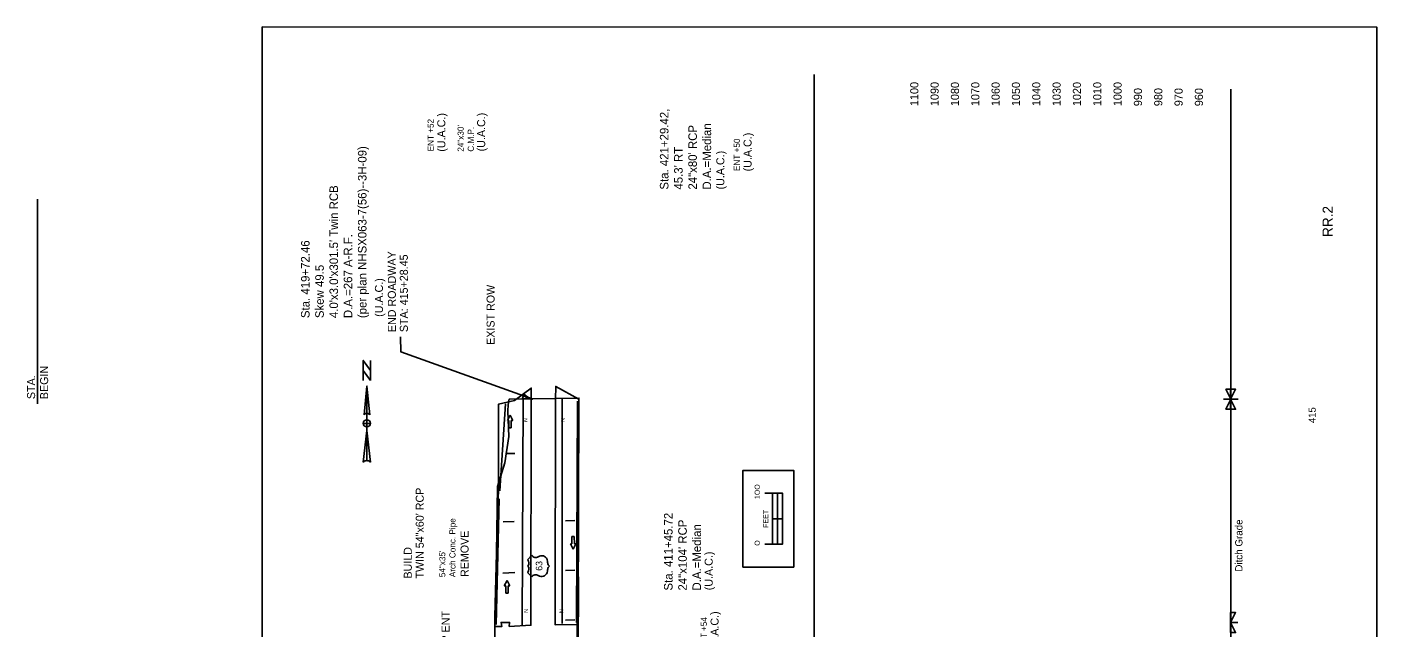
# Model space of a CAD drawing. Extents: x 15474972 to 15478172, y 8962633 to 8965955.
# Drawn here: x 15475516 to 15478172, y 8964774 to 8965955 of the extents above; entities that cross this region are included whole.
import ezdxf

# ---------------------------------------------------------------- set-up
doc = ezdxf.new("R2010")
doc.units = 0
for name, color, linetype in [('brgDimensionLines', 7, 'Continuous'), ('brgTextNormal', 7, 'Continuous'), ('Default', 7, 'Continuous'), ('dsnTextCpn', 7, 'Continuous'), ('dsnTextFinalPlan', 7, 'Continuous'), ('Existing_Right_of_Way', 7, 'Continuous'), ('Level 50', 7, 'Continuous'), ('rowdsnLineProposed', 7, 'Continuous'), ('rowdsnOverlap10', 7, 'Continuous'), ('rowdsnOverlap9', 7, 'Continuous'), ('rowdsnParcelML', 7, 'Continuous'), ('rowdsnParcelSR', 7, 'Continuous'), ('rowdsnPSConstructPlot', 7, 'Continuous'), ('rowdsnSecLines', 7, 'Continuous'), ('rowdsnShapeFeeTitle', 7, 'Continuous'), ('rowdsnStationML', 7, 'Continuous'), ('rowdsnSymbolsExisting', 7, 'Continuous'), ('rowdsnSymbolsOther', 7, 'Continuous'), ('rowdsnSymbolsProposed', 7, 'Continuous'), ('SurTxtDrainage', 7, 'Continuous')]:
    doc.layers.add(name, color=color, linetype=linetype)

msp = doc.modelspace()

# ---------------------------------------------------------------- linework, layer by layer
at = {"layer": 'brgDimensionLines'}
for p, q in [((15476500.8, 8964906.3), (15476508.8, 8964915.1)), ((15476500.8, 8964906.3), (15476508.8, 8964915.1)), ((15476538.9, 8964906.9), (15476539.2, 8964906.1)), ((15476538.9, 8964906.9), (15476539.2, 8964906.1)), ((15476540.1, 8964900.9), (15476540.2, 8964899.8)), ((15476540.1, 8964900.9), (15476540.2, 8964899.8)), ((15476508.8, 8964872.4), (15476500.8, 8964881.2)), ((15476508.8, 8964872.4), (15476500.8, 8964881.2)), ((15476539.1, 8964881.4), (15476538.9, 8964880.6)), ((15476539.1, 8964881.4), (15476538.9, 8964880.6)), ((15476540.2, 8964887.7), (15476540.1, 8964886.6)), ((15476540.2, 8964887.7), (15476540.1, 8964886.6))]:
    msp.add_line(p, q, dxfattribs=at)
for centre, radius, start, end in [((15476494.1, 8964899.9), 9.26, 318.2023, 43.3357), ((15476494.1, 8964899.9), 9.26, 318.2023, 43.3357), ((15476494.1, 8964887.6), 9.26, 316.6383, 41.7717), ((15476494.1, 8964887.6), 9.26, 316.6383, 41.7717), ((15476516.7, 8964920), 9.28, 211.4945, 303.0945), ((15476516.7, 8964920), 9.28, 211.4945, 303.0945), ((15476528.3, 8964903), 11.3, 19.6285, 125.345), ((15476528.3, 8964903), 11.3, 19.6285, 125.345), ((15476513.8, 8964898.7), 26.4, 4.9374, 16.5073), ((15476513.8, 8964898.7), 26.4, 4.9374, 16.5073), ((15476548, 8964900.2), 7.75, 182.5463, 236.993), ((15476548, 8964900.2), 7.75, 182.5463, 236.993), ((15476548, 8964887.3), 7.75, 122.981, 177.4277), ((15476548, 8964887.3), 7.75, 122.981, 177.4277), ((15476516.7, 8964867.6), 9.28, 56.8795, 148.4795), ((15476516.7, 8964867.6), 9.28, 56.8795, 148.4795), ((15476528.3, 8964884.5), 11.3, 234.629, 340.3455), ((15476528.3, 8964884.5), 11.3, 234.629, 340.3455), ((15476513.8, 8964888.8), 26.4, 343.4667, 355.0366), ((15476513.8, 8964888.8), 26.4, 343.4667, 355.0366)]:
    msp.add_arc(centre, radius, start, end, dxfattribs=at)
at = {"layer": 'brgTextNormal'}
for p, q in [((15475536.6, 8965213.4), (15475536.7, 8965616.1)), ((15476184.4, 8965247.9), (15476190.1, 8965191.6)), ((15476184.4, 8965247.9), (15476184.4, 8965101.4)), ((15476178.8, 8965191.6), (15476178.8, 8965191.6)), ((15476179, 8965192.1), (15476180.1, 8965193.3)), ((15476177.4, 8965098.6), (15476184.4, 8965160.6)), ((15476184.4, 8965167.6), (15476184.4, 8965167.6))]:
    msp.add_line(p, q, dxfattribs=at)
msp.add_lwpolyline([(15476191.5, 8965259.2), (15476177.4, 8965278.9), (15476177.4, 8965298.6), (15476191.5, 8965278.9)], close=True, dxfattribs=at)
for points in [[(15476177.4, 8965259.2), (15476177.4, 8965298.6), (15476191.5, 8965278.9), (15476191.5, 8965298.6)], [(15476178.8, 8965191.6), (15476184.4, 8965247.9), (15476184.4, 8965194.4)], [(15476184.4, 8965167.6), (15476184.4, 8965174.7), (15476177.4, 8965174.7)], [(15476191.5, 8965174.7), (15476184.4, 8965174.7), (15476184.4, 8965181.7)], [(15476184.4, 8965101.4), (15476184.4, 8965160.6), (15476191.4, 8965098.6)]]:
    msp.add_lwpolyline(points, dxfattribs=at)
for centre, radius, start, end in [((15476184.4, 8965187.4), 7.04, 90.0074, 143.1127), ((15476184.4, 8965187.4), 7.04, 36.8351, 90.0088), ((15476184.4, 8965174.7), 7.04, 89.987, 179.987), ((15476184.4, 8965174.7), 7.04, 179.987, 269.987), ((15476184.4, 8965174.7), 7.04, 359.987, 89.987), ((15476184.4, 8965174.7), 7.04, 269.987, 359.987), ((15476184.4, 8965091.2), 10.2, 89.9764, 133.606), ((15476184.4, 8965091.2), 10.2, 46.3891, 89.9876)]:
    msp.add_arc(centre, radius, start, end, dxfattribs=at)
at = {"layer": 'Default'}
msp.add_lwpolyline([(15476458.5, 8963507.6), (15476453.6, 8963983), (15476449.6, 8964035.1), (15476463.5, 8964056.5), (15476463, 8964074.2), (15476451.1, 8964099), (15476443.7, 8964141.8), (15476442.2, 8964374.2), (15476432.2, 8964442.8), (15476435.5, 8964495.1), (15476435.9, 8964794.6), (15476439.7, 8964919.1), (15476441.2, 8965050.7), (15476455.7, 8965097), (15476463.5, 8965148.9), (15476461.6, 8965199), (15476462.7, 8965212), (15476464.2, 8965222), (15476601.5, 8965224.5), (15476595.1, 8964345.6), (15476607.3, 8964246.4), (15476606.2, 8964178.2), (15476595, 8964074.4), (15476594.5, 8963511.2)], close=True, dxfattribs=at)
at = {"layer": 'dsnTextFinalPlan'}
msp.add_line((15476600.7, 8964872.6), (15476598.9, 8964307.3), dxfattribs=at)
for points in [[(15476464.5, 8964775), (15476465.2, 8964783), (15476448.5, 8964783), (15476449.9, 8964774.9), (15476436.4, 8964774.9), (15476436.2, 8964794.2), (15476438.1, 8964832.7), (15476439.9, 8964944.2), (15476443.3, 8965045.5), (15476443.4, 8965212.3), (15476474.7, 8965220), (15476507.8, 8965244), (15476507.4, 8965222.2), (15476507.4, 8965214.2), (15476507.1, 8964777.3), (15476464.5, 8964775)], [(15476555.1, 8964794.1), (15476555.3, 8965222.6), (15476556, 8965247.3), (15476601.8, 8965222.5), (15476600.4, 8964794.4), (15476600.4, 8964778.7), (15476555.2, 8964778)]]:
    msp.add_lwpolyline(points, close=True, dxfattribs=at)
at = {"layer": 'Level 50'}
msp.add_lwpolyline([(15475977.7, 8962633.8), (15475978.5, 8965954.7), (15478171.9, 8965954.2), (15478171.2, 8962633.3)], close=True, dxfattribs=at)
at = {"layer": 'rowdsnOverlap10'}
for centre, radius, start, end in [((15476476.5, 8965232.2), 16.4, 326.3938, 1.8605), ((15476499.1, 8965181.6), 42.5, 74.1271, 102.1996), ((15476522.4, 8965263.3), 42.5, 226.0547, 254.1271)]:
    msp.add_arc(centre, radius, start, end, dxfattribs=at)
at = {"layer": 'rowdsnOverlap9'}
for p, q in [((15476490, 8964777.7), (15476491.9, 8965222.7)), ((15476568.4, 8964780.9), (15476568.4, 8965223.7)), ((15476593.9, 8964983.4), (15476575.5, 8964982.8)), ((15476593.5, 8964885.7), (15476575.1, 8964885.1)), ((15476593.7, 8964788.1), (15476575.3, 8964787.5))]:
    msp.add_line(p, q, dxfattribs=at)
at = {"layer": 'rowdsnParcelSR'}
msp.add_line((15477002.4, 8964987), (15476982.4, 8964987), dxfattribs=at)
msp.add_line((15477002.4, 8964987), (15476982.4, 8964987), dxfattribs=at)
for points in [[(15477024.4, 8964892), (15476924.4, 8964892), (15476924.4, 8965082), (15477024.4, 8965082)], [(15476992.3, 8964987), (15476992.3, 8965037), (15476982.4, 8965037), (15476982.4, 8964987)], [(15477002.4, 8964937), (15477002.4, 8964987), (15476992.3, 8964987), (15476992.3, 8964937)]]:
    msp.add_lwpolyline(points, close=True, dxfattribs=at)
for points in [[(15476967.4, 8964937), (15477002.4, 8964937), (15477002.4, 8965037), (15476967.4, 8965037)], [(15476982.4, 8964937), (15476982.4, 8965037)]]:
    msp.add_lwpolyline(points, dxfattribs=at)
at = {"layer": 'rowdsnSecLines'}
for p, q in [((15476457.4, 8965213.4), (15476445.8, 8965042)), ((15476596.6, 8964782.7), (15476598.8, 8965218.6)), ((15476456.9, 8965115.6), (15476475.3, 8965115.3)), ((15476444.6, 8965026.2), (15476438.6, 8964778.6)), ((15476452.7, 8964980.7), (15476474.1, 8964981.3)), ((15476451.8, 8964880.2), (15476475.8, 8964881.1))]:
    msp.add_line(p, q, dxfattribs=at)
at = {"layer": 'rowdsnShapeFeeTitle'}
msp.add_line((15477883.8, 8962832.3), (15477884.5, 8965832.3), dxfattribs=at)
at = {"layer": 'rowdsnSymbolsExisting'}
msp.add_lwpolyline([(15476250.3, 8965344.8), (15476251, 8965315.7), (15476510.7, 8965222.5)], dxfattribs=at)
at = {"layer": 'rowdsnSymbolsOther'}
for p, q in [((15476466.5, 8965190.8), (15476460.9, 8965180.2)), ((15476471.6, 8965180), (15476466.5, 8965190.8)), ((15476460.9, 8965180.2), (15476463.9, 8965180.2)), ((15476463.9, 8965180.2), (15476463.6, 8965165.8)), ((15476463.6, 8965165.8), (15476468.3, 8965165.7)), ((15476468.3, 8965165.7), (15476468.6, 8965180.1)), ((15476468.6, 8965180.1), (15476471.6, 8965180)), ((15476592.4, 8964952.1), (15476587.7, 8964952)), ((15476587.7, 8964952), (15476587.9, 8964937.7)), ((15476592.7, 8964937.7), (15476592.4, 8964952.1)), ((15476587.9, 8964937.7), (15476584.9, 8964937.6)), ((15476584.9, 8964937.6), (15476590.5, 8964927)), ((15476590.5, 8964927), (15476595.7, 8964937.8)), ((15476595.7, 8964937.8), (15476592.7, 8964937.7)), ((15476460.5, 8964865.7), (15476454.9, 8964855.1)), ((15476465.6, 8964854.8), (15476460.5, 8964865.7)), ((15476454.9, 8964855.1), (15476457.9, 8964855)), ((15476457.9, 8964855), (15476457.6, 8964840.7)), ((15476457.6, 8964840.7), (15476462.3, 8964840.6)), ((15476462.3, 8964840.6), (15476462.6, 8964854.9)), ((15476462.6, 8964854.9), (15476465.6, 8964854.8))]:
    msp.add_line(p, q, dxfattribs=at)
at = {"layer": 'rowdsnSymbolsProposed'}
for p, q in [((15477869.6, 8965222.1), (15477884.3, 8965222.1)), ((15477898.5, 8965222.2), (15477883.7, 8965222.2)), ((15477898.4, 8964782.5), (15477883.6, 8964782.5))]:
    msp.add_line(p, q, dxfattribs=at)
for points in [[(15477884.3, 8965241.8), (15477884.3, 8965202.5), (15477874.5, 8965202.5), (15477884.3, 8965222.1), (15477874.5, 8965241.8)], [(15477883.7, 8965202.5), (15477883.7, 8965241.8), (15477893.6, 8965241.8), (15477883.7, 8965222.2), (15477893.6, 8965202.5)], [(15477883.6, 8964762.8), (15477883.6, 8964802.2), (15477893.5, 8964802.2), (15477883.6, 8964782.5), (15477893.5, 8964762.8)]]:
    msp.add_lwpolyline(points, close=True, dxfattribs=at)
at = {"layer": 'SurTxtDrainage'}
msp.add_line((15477063.8, 8962726.5), (15477064.5, 8965861.5), dxfattribs=at)

# ---------------------------------------------------------------- texts
at = {"layer": 'brgDimensionLines'}
msp.add_text('63', height=12.87, rotation=89.987, dxfattribs=at).set_placement((15476529.7, 8964884.6))
at = {"layer": 'brgTextNormal'}
for s, p in [('STA.             ', (15475531.7, 8965222.4)), ('BEGIN                     ', (15475557.3, 8965222.4))]:
    msp.add_text(s, height=15.749, rotation=89.987, dxfattribs=at).set_placement(p)
at = {"layer": 'dsnTextCpn'}
msp.add_text('Ditch Grade', height=14.4, rotation=89.987, dxfattribs=at).set_placement((15477907.2, 8964882.9))
at = {"layer": 'dsnTextFinalPlan'}
for p in [(15476500.1, 8965177.3), (15476573.9, 8965177.9), (15476501.2, 8964802), (15476570.9, 8964801.5)]:
    msp.add_text('N', height=7.5, rotation=89.987, dxfattribs=at).set_placement(p)
at = {"layer": 'Existing_Right_of_Way'}
for s, p in [('ENT +52', (15476315.9, 8965710)), ('ENT +50', (15476918.4, 8965671.4)), ('ENT +54', (15476853.5, 8964729.5))]:
    msp.add_text(s, height=12, rotation=90, dxfattribs=at).set_placement(p)
at = {"layer": 'rowdsnLineProposed'}
msp.add_text('415', height=14, rotation=89.987, dxfattribs=at).set_placement((15478051.3, 8965175.2))
at = {"layer": 'rowdsnOverlap10'}
for s, height, p in [('(U.A.C.)', 15.75, (15476338.8, 8965709.3)), ('(U.A.C.)', 15.75, (15476417.2, 8965709.9)), ('(U.A.C.)', 15.75, (15476941.4, 8965670.6)), ('(U.A.C.)', 15.75, (15476887.8, 8965635)), ('END ROADWAY', 15.749, (15476241.5, 8965354.2)), ('STA: 415+28.45', 15.749, (15476265.1, 8965354.3)), ('(U.A.C.)', 15.75, (15476216.1, 8965384.3)), ('EXIST ROW', 15.75, (15476435.8, 8965329.2)), ('TWIN 54"x60\' RCP', 15.749, (15476296.4, 8964869.3)), ('REMOVE', 15.75, (15476384.6, 8964872.3)), ('BUILD', 15.75, (15476272.8, 8964869.3)), ('(U.A.C.)', 15.75, (15476864.9, 8964846.3)), ('PROP ENT', 15.75, (15476347.1, 8964697.7)), ('(U.A.C.)', 15.75, (15476876.5, 8964728.7))]:
    msp.add_text(s, height=height, rotation=90.0316, dxfattribs=at).set_placement(p)
at = {"layer": 'rowdsnParcelML'}
msp.add_text('RR.2', height=20, rotation=89.987, dxfattribs=at).set_placement((15478084.9, 8965541.5))
at = {"layer": 'rowdsnParcelSR'}
for s, p in [('1OO', (15476957.4, 8965025.7)), ('1OO', (15476957.4, 8965025.7)), ('FEET', (15476974.4, 8964969.1)), ('O', (15476957.4, 8964933.8)), ('O', (15476957.4, 8964933.8))]:
    msp.add_text(s, height=10, rotation=89.987, dxfattribs=at).set_placement(p)
at = {"layer": 'rowdsnPSConstructPlot'}
for s, p in [('1100', (15477269.5, 8965799)), ('1090', (15477309.5, 8965799)), ('1080', (15477349.5, 8965798.9)), ('1070', (15477389.5, 8965798.9)), ('1060', (15477429.5, 8965798.9)), ('1050', (15477469.5, 8965798.9)), ('1040', (15477509.5, 8965798.9)), ('1030', (15477549.5, 8965798.9)), ('1020', (15477589.5, 8965798.9)), ('1010', (15477629.5, 8965798.9)), ('1000', (15477669.5, 8965798.9)), ('990', (15477709.5, 8965798.9)), ('980', (15477749.5, 8965798.9)), ('970', (15477789.5, 8965798.8)), ('960', (15477829.5, 8965798.8))]:
    msp.add_text(s, height=16, rotation=89.987, dxfattribs=at).set_placement(p)
at = {"layer": 'rowdsnStationML'}
for s, height, p in [('Sta. 421+29.42, ', 16.8, (15476777.8, 8965634.7)), ('24"x30\'', 12, (15476374.9, 8965709.3)), ('C.M.P.', 12, (15476394.9, 8965709.3)), ('24"x80\' RCP', 16.8, (15476833.8, 8965634.7)), ('D.A.=Median', 16.8, (15476861.8, 8965634.7)), ('(per plan NHSX063-7(56)--3H-09)', 16.8, (15476183.7, 8965381.8)), ("45.3' RT", 16.8, (15476805.8, 8965634.7)), ("4.0'x3.0'x301.5' Twin RCB", 16.8, (15476127.7, 8965381.8)), ('Sta. 419+72.46', 16.8, (15476071.7, 8965381.8)), ('D.A.=267 A-R.F.', 16.8, (15476155.7, 8965381.8)), ('Skew 49.5', 16.8, (15476099.7, 8965381.8)), ('Sta. 411+45.72', 16.8, (15476785.9, 8964845.7)), ('Arch Conc. Pipe', 12, (15476358.8, 8964872)), ('24"x104\' RCP', 16.8, (15476813.9, 8964845.7)), ('D.A.=Median', 16.8, (15476841.9, 8964845.7)), ('54"x35\'', 12, (15476338.8, 8964872))]:
    msp.add_text(s, height=height, rotation=90, dxfattribs=at).set_placement(p)

doc.saveas('drawing.dxf')
